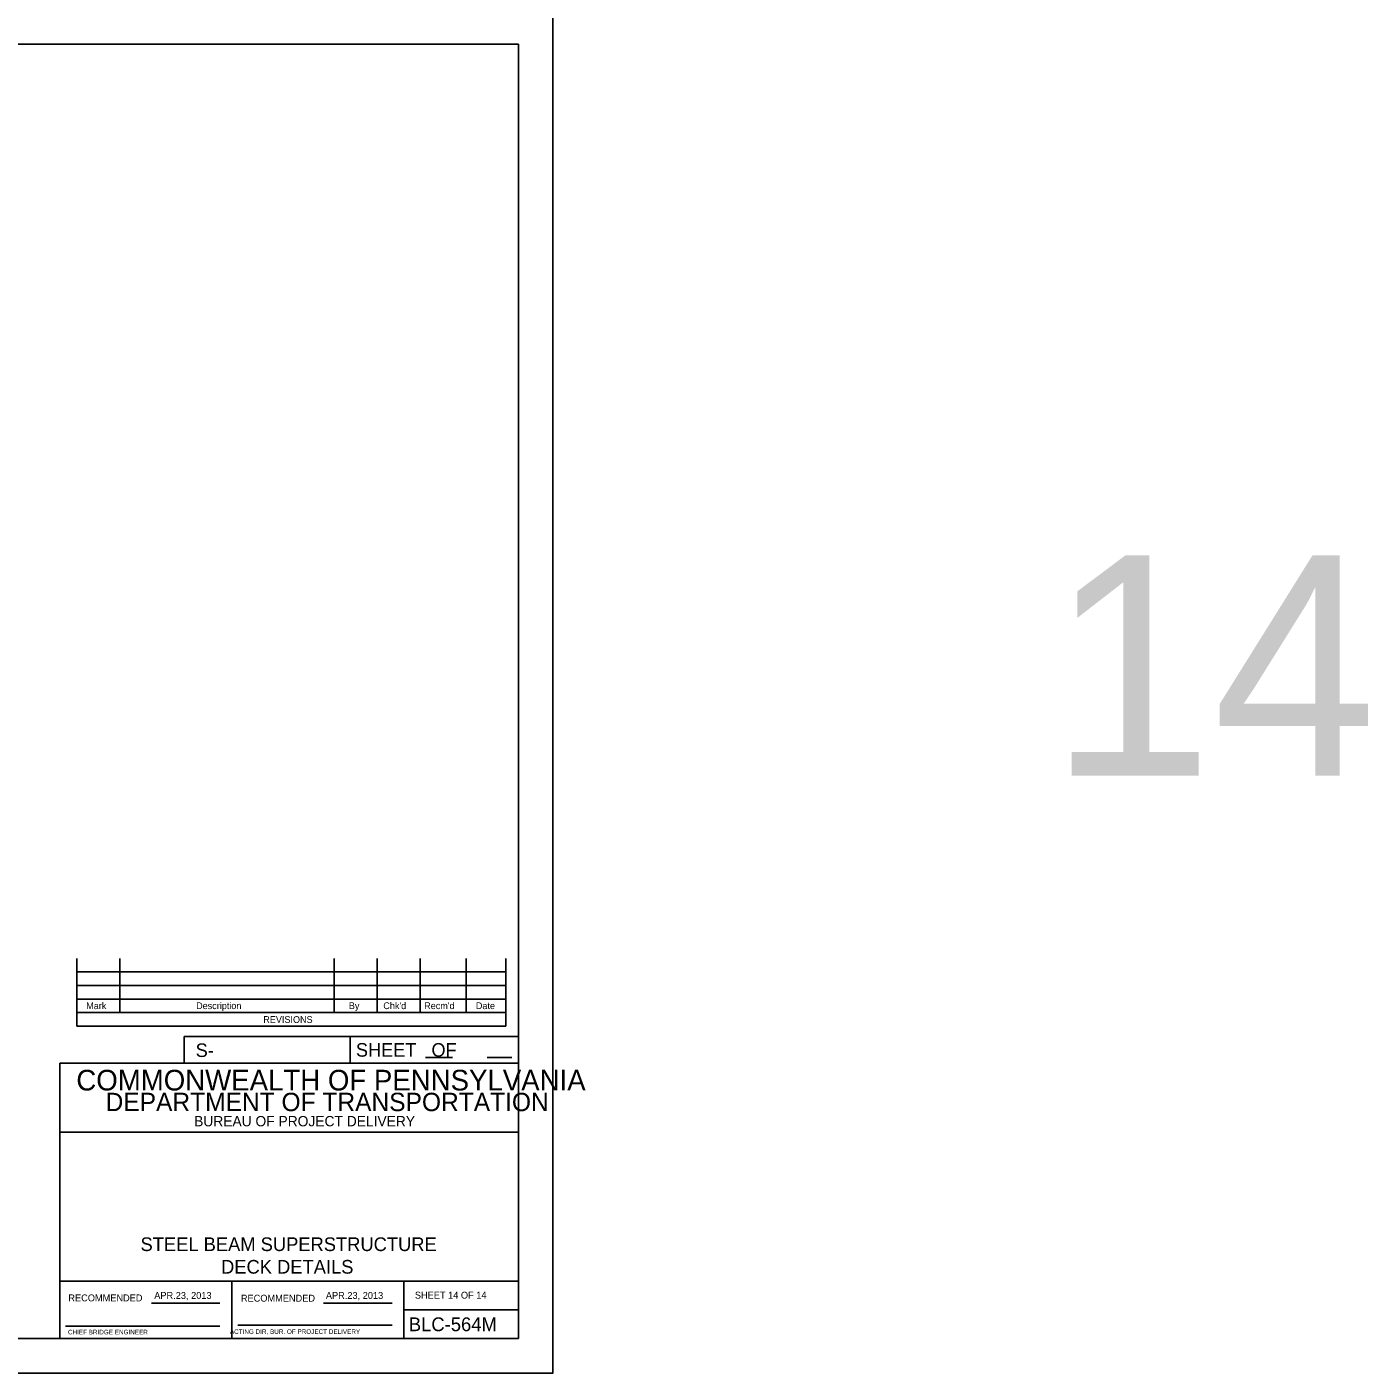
# Model space of a CAD drawing. Extents: x 638175 to 640495, y 294277 to 298435.
# Drawn here: x 639888 to 640473, y 294277 to 294864 of the extents above; entities that cross this region are included whole.
import ezdxf

# ---------------------------------------------------------------- set-up
doc = ezdxf.new("R2010")
doc.units = 0
for name, color, linetype in [('1', 7, 'Continuous'), ('2', 7, 'Continuous'), ('4', 7, 'Continuous'), ('53', 7, 'Continuous'), ('PLT-BNDY', 7, 'Continuous')]:
    doc.layers.add(name, color=color, linetype=linetype)

msp = doc.modelspace()

# ---------------------------------------------------------------- linework, layer by layer
at = {"layer": '2'}
for p, q in [((639316.46, 294856.46), (640102.46, 294856.46)), ((640102.46, 294856.46), (640102.46, 294292.46)), ((639909.92, 294458.15), (639909.92, 294428.62)), ((639928.62, 294458.15), (639928.62, 294434.53)), ((640022.13, 294458.15), (640022.13, 294434.53)), ((640040.83, 294458.15), (640040.83, 294434.53)), ((640059.53, 294458.15), (640059.53, 294434.53)), ((640079.59, 294458.15), (640079.59, 294434.53)), ((640096.94, 294458.15), (640096.94, 294428.62)), ((640096.94, 294452.24), (639909.92, 294452.24)), ((640096.94, 294446.34), (639909.92, 294446.34)), ((640096.94, 294440.43), (639909.92, 294440.43)), ((640096.94, 294434.53), (639909.92, 294434.53)), ((640096.94, 294428.62), (639909.92, 294428.62)), ((640102.46, 294424.11), (639956.78, 294424.11)), ((639956.78, 294424.11), (639956.78, 294412.46)), ((640029.09, 294424.11), (640029.09, 294412.46)), ((640102.46, 294412.46), (639902.46, 294412.46)), ((639902.46, 294412.46), (639902.46, 294292.46)), ((640061.95, 294415), (640073.6, 294415)), ((640088.83, 294415), (640099.56, 294415)), ((640102.46, 294382.46), (639902.46, 294382.46)), ((640102.46, 294317.46), (639902.46, 294317.46)), ((639977.46, 294292.46), (639977.46, 294317.46)), ((640052.46, 294317.46), (640052.46, 294292.46)), ((639942.42, 294307.96), (639972.19, 294307.96)), ((640017.42, 294307.96), (640047.33, 294307.96)), ((640052.46, 294304.96), (640102.46, 294304.96)), ((639904.96, 294297.96), (639972.19, 294297.96)), ((639980.08, 294298.33), (640047.33, 294298.33)), ((640102.46, 294292.46), (639316.46, 294292.46))]:
    msp.add_line(p, q, dxfattribs=at)
at = {"layer": 'PLT-BNDY'}
msp.add_lwpolyline([(639276.46, 294871.46), (640117.46, 294871.46), (640117.46, 294277.46), (639276.46, 294277.46)], close=True, dxfattribs=at)

# ---------------------------------------------------------------- texts
at = {"layer": '1'}
msp.add_text('SHEET 14 OF 14', height=3, dxfattribs=at).set_placement((640057.27, 294309.9))
at = {"layer": '2'}
for s, height, p in [('Mark', 2.952, (639914.02, 294436.03)), ('Description', 2.9523, (639961.92, 294436.03)), ('By', 2.952, (640028.49, 294436.03)), ("Chk'd", 2.952, (640043.52, 294436.03)), ("Recm'd", 2.953, (640061.33, 294436.03)), ('Date', 2.952, (640083.86, 294436.03)), ('REVISIONS', 2.952, (639991.2, 294430.01)), ('S-', 5.905, (639961.73, 294415.17)), ('COMMONWEALTH OF PENNSYLVANIA', 9, (639909.71, 294400.58)), ('DEPARTMENT OF TRANSPORTATION', 8.0002, (639922.46, 294391.58)), ('BUREAU OF PROJECT DELIVERY', 4.5, (639961.05, 294384.96)), ('DECK DETAILS', 5.9714, (639972.8, 294320.77)), ('APR.23, 2013', 3, (639943.67, 294309.77)), ('APR.23, 2013', 3, (640018.48, 294309.77)), ('BLC-564M', 6, (640054.64, 294295.71)), ('CHIEF BRIDGE ENGINEER', 2.0002, (639906.05, 294294.33)), ('  ACTING DIR, BUR. OF PROJECT DELIVERY', 2.0002, (639975.11, 294294.51))]:
    msp.add_text(s, height=height, dxfattribs=at).set_placement(p)
for s, height, p in [('SHEET   OF', 5.907, (640031.58, 294415.31)), ('RECOMMENDED', 3, (639906.23, 294308.71)), ('RECOMMENDED', 3, (639981.44, 294308.58))]:
    msp.add_text(s, height=height, rotation=360, dxfattribs=at).set_placement(p)
at = {"layer": '4'}
msp.add_text('STEEL BEAM SUPERSTRUCTURE', height=5.9714, dxfattribs=at).set_placement((639937.69, 294330.61))
at = {"layer": '53'}
msp.add_text('14', height=96, dxfattribs=at).set_placement((640333.73, 294537.69))

doc.saveas('drawing.dxf')
